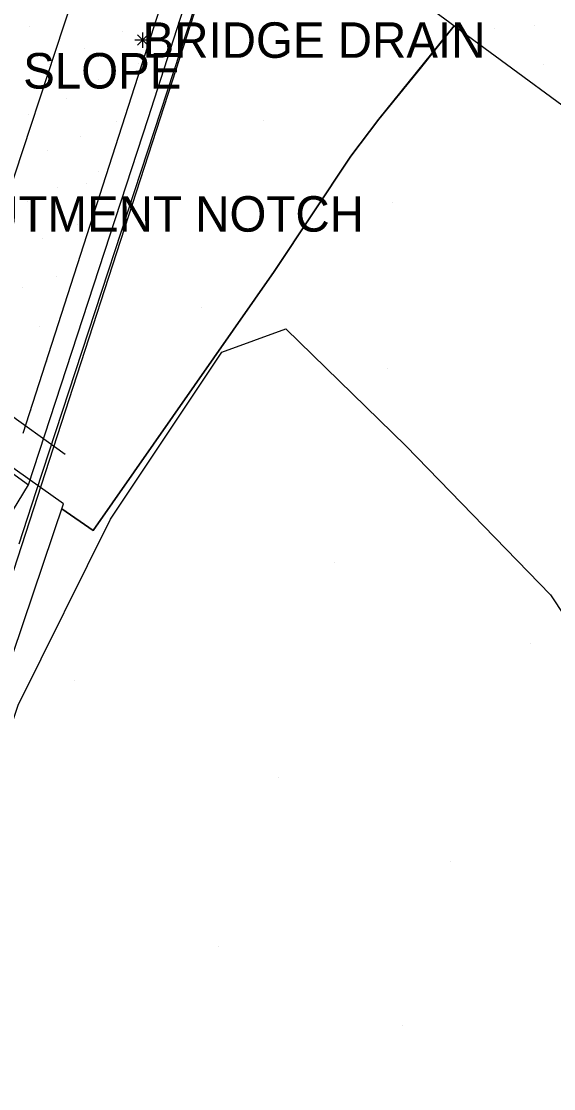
# Model space of a CAD drawing. Extents: x 0 to 1739264, y 0 to 465304.
# Drawn here: x 1738822.1 to 1738849.1, y 464509.2 to 464563.4 of the extents above; entities that cross this region are included whole.
import ezdxf

# ---------------------------------------------------------------- set-up
doc = ezdxf.new("R2010")
doc.units = 0
for name, color, linetype in [('Default', 7, 'Continuous'), ('S_Ground_SpotElevation', 7, 'Continuous'), ('S_Misc_MiscItems', 7, 'Continuous'), ('S_Terrain_Holes', 7, 'Continuous'), ('S_Terrain_Imported_Contours', 7, 'Continuous'), ('S_Terrain_Low_Points', 7, 'Continuous'), ('S_Terrain_Major_Contours_Label', 7, 'Continuous'), ('S_Terrain_Minor_Contours', 7, 'Continuous'), ('S_Terrain_Minor_Contours_Label', 7, 'Continuous'), ('S_Terrain_Spots', 7, 'Continuous'), ('S_Terrain_Triangles', 7, 'Continuous'), ('S_Terrain_Voids', 7, 'Continuous'), ('S_Terrain_XSC', 7, 'Continuous'), ('S_Text', 7, 'Continuous')]:
    doc.layers.add(name, color=color, linetype=linetype)

# ---------------------------------------------------------------- blocks, each defined once
blk = doc.blocks.new('POINT_DISPLAY')
at = {"layer": 'Default'}
blk.add_line((0, 0), (0, 0), dxfattribs=at)

msp = doc.modelspace()

# ---------------------------------------------------------------- linework, layer by layer
at = {"layer": 'S_Misc_MiscItems'}
for p, q in [((1738828.680925, 464562.4312), (1738827.895075, 464562.4312)), ((1738828.550081, 464562.169119), (1738828.025919, 464562.693281)), ((1738828.550081, 464562.693281), (1738828.025919, 464562.169119)), ((1738828.288, 464562.824125), (1738828.288, 464562.038275))]:
    msp.add_line(p, q, dxfattribs=at)
at = {"layer": 'S_Terrain_Holes'}
msp.add_lwpolyline([(1739170.588308, 464325.500373), (1739152.552907, 464338.483527), (1739114.826696, 464366.236518), (1739080.0463, 464391.153388), (1739045.200704, 464417.071418), (1738978.615499, 464465.012885), (1738944.577802, 464489.97779), (1738904.0454, 464519.108802), (1738859.5087, 464551.815192), (1738837.105501, 464568.288306), (1738799.9269, 464594.941993), (1738767.332898, 464618.452308), (1738734.240804, 464642.564887), (1738701.246496, 464666.335303), (1738672.330098, 464687.406394), (1738626.181707, 464720.896705), (1738547.219503, 464778.355994), (1738497.724386, 464814.494201), (1738418.864705, 464871.408801)], dxfattribs=at)
at = {"layer": 'S_Terrain_Imported_Contours'}
msp.add_lwpolyline([(1738816.833754, 464540.526168), (1738828.844899, 464576.996803), (1738841.383399, 464615.664314), (1738851.1298, 464645.487891), (1738867.0642, 464694.79), (1738880.224773, 464736.284008)], dxfattribs=at)
at = {"layer": 'S_Terrain_Low_Points'}
for points in [[(1738851.7415, 464633.401588), (1738839.363599, 464595.771888), (1738822.210698, 464542.4672)], [(1738824.361402, 464541.409187), (1738811.574601, 464550.613898), (1738793.8952, 464563.371192)], [(1738824.192507, 464538.643234), (1738825.778961, 464537.554563), (1738834.95548, 464550.692309), (1738838.840101, 464556.540687), (1738840.265901, 464558.414985), (1738844.084702, 464563.156487)]]:
    msp.add_lwpolyline(points, dxfattribs=at)
at = {"layer": 'S_Terrain_Major_Contours_Label'}
msp.add_line((1738822.141572, 464536.77828), (1738815.329301, 464515.763404), dxfattribs=at)
msp.add_lwpolyline([(1738885.395159, 464732.452095), (1738884.2943, 464729.028999), (1738875.3401, 464701.327995), (1738857.6966, 464646.653999), (1738844.752799, 464606.659614), (1738829.9694, 464560.926002), (1738822.141572, 464536.77828)], dxfattribs=at)
at = {"layer": 'S_Terrain_Minor_Contours'}
msp.add_lwpolyline([(1738822.502035, 464539.871865), (1738828.574695, 464558.460113), (1738842.68621, 464602.312192), (1738844.286302, 464607.201361)], dxfattribs=at)
at = {"layer": 'S_Terrain_Minor_Contours_Label'}
msp.add_line((1738820.8128, 464537.091335), (1738822.502035, 464539.871865), dxfattribs=at)
msp.add_lwpolyline([(1738794.472612, 464560.340831), (1738808.854402, 464549.78379), (1738822.502035, 464539.871865)], dxfattribs=at)
at = {"layer": 'S_Terrain_Spots'}
msp.add_lwpolyline([(1738844.084702, 464563.156487), (1738842.3705, 464560.990394), (1738840.265901, 464558.414985), (1738838.840101, 464556.540687), (1738834.95548, 464550.692309), (1738825.778961, 464537.554563), (1738824.192507, 464538.643234)], dxfattribs=at)
at = {"layer": 'S_Terrain_Triangles'}
msp.add_lwpolyline([(1738885.339743, 464732.493165), (1738884.4636, 464729.823402), (1738878.6737, 464712.005698), (1738871.4064, 464689.647605), (1738862.8085, 464662.946113), (1738850.8758, 464625.801398), (1738841.409499, 464596.833595), (1738830.533101, 464562.882606), (1738822.877599, 464539.516792), (1738822.019587, 464536.864414)], dxfattribs=at)
at = {"layer": 'S_Terrain_Voids'}
for points in [[(1738826.663598, 464538.125495), (1738832.310899, 464546.601691), (1738835.552598, 464547.78971)], [(1738835.552598, 464547.78971), (1738841.632501, 464541.839301), (1738848.970901, 464534.291206), (1738853.3325, 464527.698493), (1738854.5804, 464522.518714), (1738856.9582, 464515.207191), (1738861.124, 464497.744514), (1738865.8073, 464476.570686), (1738871.0524, 464464.024299), (1738877.9813, 464453.856605), (1738886.7087, 464445.997199), (1738901.103502, 464437.572791)], [(1738732.942598, 464244.125001), (1738760.736898, 464334.173501), (1738791.830404, 464432.979804), (1738815.289899, 464508.737312), (1738821.9792, 464528.690314), (1738826.663598, 464538.125495)]]:
    msp.add_lwpolyline(points, dxfattribs=at)
at = {"layer": 'S_Terrain_XSC'}
msp.add_lwpolyline([(1738814.14452, 464513.988285), (1738813.552795, 464509.732721), (1738814.803017, 464509.279343), (1738820.147802, 464526.716407), (1738824.280564, 464538.902891), (1738807.061256, 464551.125116), (1738792.638793, 464561.797986), (1738788.885801, 464549.688605), (1738782.975453, 464532.328202), (1738784.214099, 464531.891033), (1738786.303217, 464535.461028)], dxfattribs=at)

# ---------------------------------------------------------------- block references
at = {"layer": 'S_Ground_SpotElevation'}
for p in [(1738822.552806, 464563.112724), (1738827.289806, 464562.865593), (1738846.147899, 464563.042226), (1738848.182506, 464563.174307), (1738825.317805, 464562.008476), (1738828.103603, 464561.265129), (1738830.084599, 464561.242498), (1738823.578807, 464561.198601), (1738848.639293, 464561.179708), (1738826.070705, 464560.414177), (1738824.423503, 464559.449577), (1738822.501704, 464558.634697), (1738826.978099, 464558.3153), (1738834.400803, 464558.32658), (1738825.165599, 464557.55413), (1738823.476207, 464556.814323), (1738826.048198, 464555.787895), (1738823.983302, 464554.943413), (1738825.4246, 464555.175695), (1738822.4584, 464554.238029), (1738840.972001, 464554.201702), (1738824.970195, 464553.087028), (1738823.192393, 464552.350578), (1738823.945796, 464550.416374), (1738822.210902, 464549.857719), (1738831.286103, 464548.871685), (1738823.043605, 464547.892082), (1738823.4817, 464546.132927), (1738840.696107, 464545.778179), (1738822.645305, 464543.631828), (1738838.040696, 464535.920574), (1738847.9749, 464531.807964), (1738824.843903, 464529.940411), (1738835.190003, 464525.018963), (1738843.9115, 464520.778668), (1738832.151002, 464516.447918), (1738841.480302, 464512.418377)]:
    msp.add_blockref('POINT_DISPLAY', p, dxfattribs=at)

# ---------------------------------------------------------------- texts
at = {"layer": 'S_Text'}
for s, p in [('BRIDGE DRAIN', (1738828.288, 464561.5312)), ('CONC SLOPE', (1738814.477, 464559.9746)), ('TOP OF ABUTMENT NOTCH', (1738807.42, 464552.7118))]:
    msp.add_text(s, height=1.8, dxfattribs=at).set_placement(p)

doc.saveas('drawing.dxf')
